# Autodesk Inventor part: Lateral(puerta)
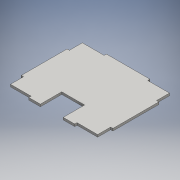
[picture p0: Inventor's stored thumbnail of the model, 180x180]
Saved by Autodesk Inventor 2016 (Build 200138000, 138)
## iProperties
Created: 2016-06
Part Number: Lateral(puerta)
Material: Genérico
Document SubType Name: Modeling
Designer: adm
Density: 1 g/cm^3
Appearance: Valor por defecto
Author: adm
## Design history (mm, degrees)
sketch "Boceto1"
  geometry: L1 (1.5, 50)-(28.5, 50); L2 (28.5, 50)-(28.5, 47); L3 (57, -47)-(57, -30); L4 (30, -47)-(57, -47); L5 (57, -30)-(60, -30); L6 (60, 30)-(60, -30); L7 (57, 30)-(60, 30); L8 (57, 47)-(28.5, 47); L9 (57, 30)-(57, 47); L10 (42, 27)-(45, 27); L11 (45, 27)-(45, 37); L12 (45, 37)-(42, 37); L13 (42, 37)-(42, 27); L14 (45, 27)-(42, 37); L15 (42, 27)-(45, 37); L16 (-45, 27)-(-45, 37); L17 (-42, 37)-(-42, 27); L18 (-42, 27)-(-45, 37); L19 (-45, 27)-(-42, 37); L20 (-45, 37)-(-42, 37); L21 (-57, 30)-(-57, 47); L22 (-57, 47)-(-28.5, 47); L23 (-28.5, 50)-(-28.5, 47); L24 (1.5, 50)-(-28.5, 50); L25 (30, -47)-(30, -50); L26 (-42, 27)-(-45, 27); L27 (-57, 30)-(-60, 30); L28 (-60, 30)-(-60, -30); L29 (1.5, -22)-(15, -22); L30 (1.5, -22)-(-15, -22); L31 (30, -50)-(15, -50); L32 (15, -50)-(15, -22); L33 (-15, -50)-(-15, -22); L34 (-30, -50)-(-15, -50); L35 (-30, -47)-(-30, -50); L36 (-57, -30)-(-60, -30); L37 (-57, -47)-(-57, -30); L38 (-30, -47)-(-57, -47); 3 further points
  constraints: 76 end point, 4 midpoint, 4 parallel, 4 perpendicular, 2 horizontal
  dimensions: "d0" = 94 distance of L3.start L8.start; "d1" = 3 distance of L12.end L11.end; "d2" = 100 distance between parallel lines of L31 L1; "d5" = 28 distance between parallel lines of L29 L31; "d8" = 120 distance between parallel lines of L6 L28; "d9" = 31.5 distance between parallel lines of L23 L28; "d10" = 31.5 distance between parallel lines of L2 L6; "d11" = 3 distance between parallel lines of L6 L3; "d13" = 3 distance between parallel lines of L6 L9; "d14" = 30 distance between parallel lines of L32 L33; "d15" = 15 distance of L25.end L31.end; "d16" = 15 distance between parallel lines of L25 L32
extrude "Extrusión1" new body sketch "Boceto1" distance "d3" = 3; taper "d4" = 0 deg
sketch "Boceto2"
  geometry: L1 (-45, 37)-(-42, 37) reference; L2 (-42, 37)-(-42, 27) reference; L3 (-45, 37)-(-42, 37); L4 (-42, 37)-(-42, 27); L5 (-42, 27)-(-45, 27); L6 (-45, 27)-(-45, 37); L7 (45, 37)-(42, 37) reference; L8 (45, 27)-(45, 37) reference; L9 (42, 37)-(45, 37); L10 (45, 37)-(45, 27); L11 (45, 27)-(42, 27); L12 (42, 27)-(42, 37); 1 further point
  constraints: 16 end point, 4 parallel, 2 horizontal, 2 perpendicular
extrude "Extrusión2" join sketch "Boceto2" distance "d6" = 3; taper "d7" = 0 deg
node "Sólido1"
